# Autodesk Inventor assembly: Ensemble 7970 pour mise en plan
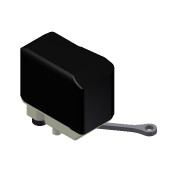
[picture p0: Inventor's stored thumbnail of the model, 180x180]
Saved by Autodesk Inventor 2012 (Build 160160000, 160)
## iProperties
Created: 2011-10
Part Number: Ensemble 7970 pour mise en plan
Document SubType Name: Assembly
Designer: Laur
Author: Laur
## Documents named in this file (11)
- D:\Formulaire\Sujet CIM 4 Poissy\Modélisation_7970_shimano\Ensemble 7970 pour mise en plan.iam
- D:\Formulaire\Sujet CIM 4 Poissy\Modélisation_7970_shimano\Fond_boitier.ipt
- D:\Formulaire\Sujet CIM 4 Poissy\Modélisation_7970_shimano\Sous-ensemble 7970.iam
- D:\Formulaire\Sujet CIM 4 Poissy\Modélisation_7970_shimano\éléments standards\ISO 3601-1(5)\ISO 3601-1 - A 0035 G 4(5).ipt
- D:\Formulaire\Sujet CIM 4 Poissy\Modélisation_7970_shimano\mobile de sortie.iam
- D:\Formulaire\Sujet CIM 4 Poissy\Modélisation_7970_shimano\Montage PCB_FD.iam
- D:\Formulaire\Sujet CIM 4 Poissy\Modélisation_7970_shimano\Support pistes capteur angulaire.ipt
- D:\Formulaire\Sujet CIM 4 Poissy\Modélisation_7970_shimano\support_curseur_equipe.iam
- D:\Formulaire\Sujet CIM 4 Poissy\Modélisation_7970_shimano\biellette.ipt
- D:\Formulaire\Sujet CIM 4 Poissy\Modélisation_7970_shimano\PalierØ4-2_normal.ipt
- D:\Formulaire\Sujet CIM 4 Poissy\Modélisation_7970_shimano\PalierØ4-2_etroit.ipt
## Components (11 placed, 10 different names)
1. Fond_boitier:1 — appui plan platine/boîtier, coaxialité axe de sortie, orientation platine boîtier, coaxialité palier / fond boîtier, appui plan palier / fond boîtier, Placage:17, Tangente:2
2. Sous-ensemble 7970:1 [sub-assembly] — appui plan platine/boîtier, coaxialité axe de sortie, orientation platine boîtier, coaxialité joint/logement, pos axiale joint/logement, Logement palier / platine, appui plan PCB / cage, centrage PBC / pilier1 cage, appui plan, centrage pilier1 Map, centrage pilier2 Map, centrage PCB / pilier2 cage
3. ISO 3601-1 hydraulique (Intérieurs) A 0035 G:1 — coaxialité joint/logement, pos axiale joint/logement
4. PalierØ4-2_normal:1 — Logement palier / platine, Logement:2
5. mobile de sortie:1 [sub-assembly] — Logement:2, centrage support curseur/arbre de sortie, pos angulaire plot / secteur denté, appui plan support / secteur denté, pivot biellette / maneton, Angle:2
6. Montage PCB_FD:1 [sub-assembly] — appui plan PCB / cage, centrage PBC / pilier1 cage, centrage PCB / pilier2 cage
7. Support pistes capteur angulaire:1 — appui plan, centrage pilier1 Map, centrage pilier2 Map, Angle:2
8. support_curseur_equipe:1 [sub-assembly] — centrage support curseur/arbre de sortie, pos angulaire plot / secteur denté, appui plan support / secteur denté
9. biellette:1 — pivot biellette / maneton
10. PalierØ4-2_etroit:1 — coaxialité palier / fond boîtier, appui plan palier / fond boîtier
11. ISO 3601-1 hydraulique (Intérieurs) A 0035 G:2 — Placage:17, Tangente:2
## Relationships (22: Mate 15, Insert 3, Angle 2, Tangent 2)
- appui plan platine/boîtier [Mate]: Fond_boitier:1 ↔ Sous-ensemble 7970:1
- coaxialité axe de sortie [Mate]: Fond_boitier:1 ↔ Sous-ensemble 7970:1
- orientation platine boîtier [Angle]: Fond_boitier:1 ↔ Sous-ensemble 7970:1
- coaxialité joint/logement [Mate]: Sous-ensemble 7970:1 ↔ ISO 3601-1 hydraulique (Intérieurs) A 0035 G:1
- pos axiale joint/logement [Tangent]: Sous-ensemble 7970:1 ↔ ISO 3601-1 hydraulique (Intérieurs) A 0035 G:1
- Logement palier / platine [Insert]: Sous-ensemble 7970:1 ↔ PalierØ4-2_normal:1
- Logement:2 [Insert]: PalierØ4-2_normal:1 ↔ mobile de sortie:1
- appui plan PCB / cage [Mate]: Sous-ensemble 7970:1 ↔ Montage PCB_FD:1
- centrage PBC / pilier1 cage [Mate]: Sous-ensemble 7970:1 ↔ Montage PCB_FD:1
- appui plan [Mate]: Sous-ensemble 7970:1 ↔ Support pistes capteur angulaire:1
- centrage pilier1 Map [Mate]: Sous-ensemble 7970:1 ↔ Support pistes capteur angulaire:1
- centrage pilier2 Map [Mate]: Sous-ensemble 7970:1 ↔ Support pistes capteur angulaire:1
- centrage support curseur/arbre de sortie [Mate]: mobile de sortie:1 ↔ support_curseur_equipe:1
- pos angulaire plot / secteur denté [Mate]: mobile de sortie:1 ↔ support_curseur_equipe:1
- appui plan support / secteur denté [Mate]: mobile de sortie:1 ↔ support_curseur_equipe:1
- centrage PCB / pilier2 cage [Mate]: Sous-ensemble 7970:1 ↔ Montage PCB_FD:1
- pivot biellette / maneton [Insert]: mobile de sortie:1 ↔ biellette:1
- coaxialité palier / fond boîtier [Mate]: Fond_boitier:1 ↔ PalierØ4-2_etroit:1
- appui plan palier / fond boîtier [Mate]: Fond_boitier:1 ↔ PalierØ4-2_etroit:1
- Placage:17 [Mate]: Fond_boitier:1 ↔ ISO 3601-1 hydraulique (Intérieurs) A 0035 G:2
- Tangente:2: Fond_boitier:1 ↔ ISO 3601-1 hydraulique (Intérieurs) A 0035 G:2
- Angle:2: mobile de sortie:1 ↔ Support pistes capteur angulaire:1
